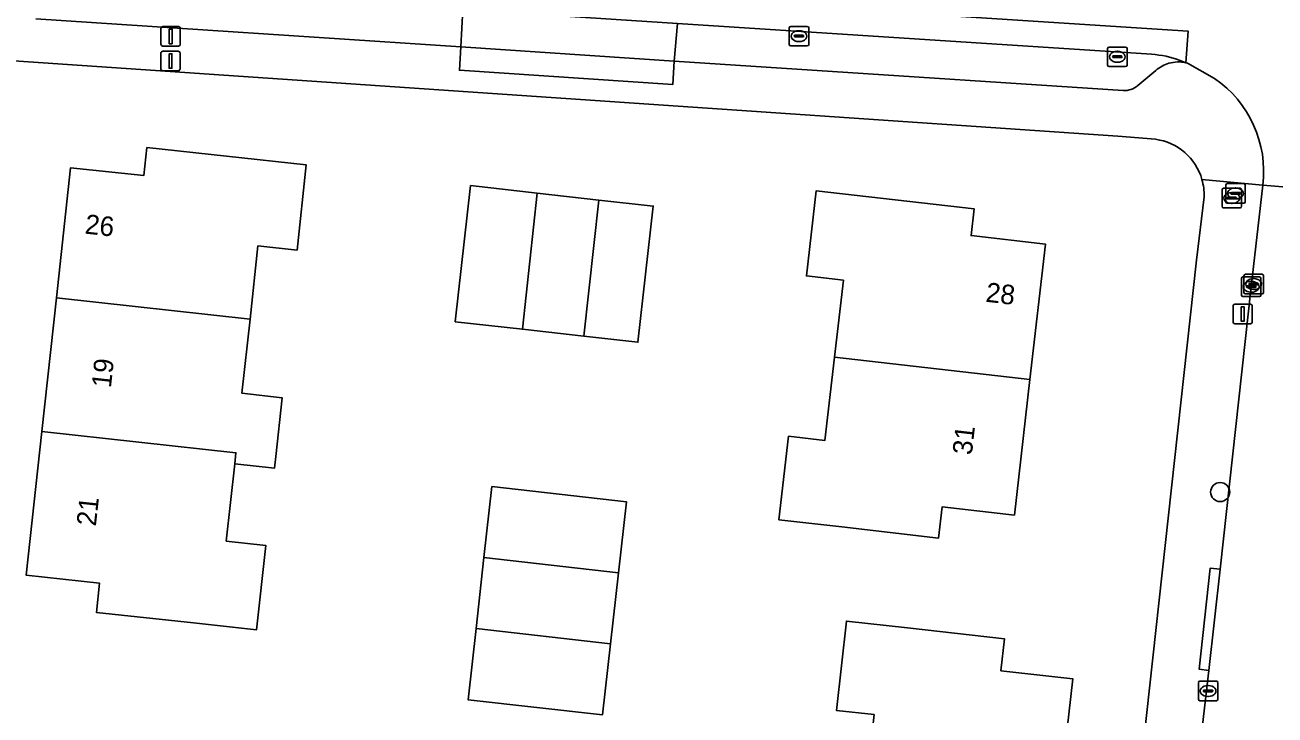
# Model space of a CAD drawing. Extents: x 162396 to 163643, y 386452 to 387406.
# Drawn here: x 162787.9 to 162852, y 386553.7 to 386589 of the extents above; entities that cross this region are included whole.
import ezdxf

# ---------------------------------------------------------------- set-up
doc = ezdxf.new("R2010")
doc.units = 0
for name, color, linetype in [('IMGEO_Boom', 7, 'Continuous'), ('IMGEO_Brandkraan', 7, 'Continuous'), ('IMGEO_Erf', 7, 'Continuous'), ('IMGEO_Kolk', 7, 'Continuous'), ('IMGEO_Lichtmast', 7, 'Continuous'), ('IMGEO_Pand', 7, 'Continuous'), ('IMGEO_Pand_nummerreeks', 7, 'Continuous'), ('IMGEO_Parkeervlak_open', 7, 'Continuous'), ('IMGEO_Rijbaan_lokaal_gesloten', 7, 'Continuous'), ('IMGEO_Rijbaan_lokaal_open', 7, 'Continuous'), ('IMGEO_Voetpad_open', 7, 'Continuous')]:
    doc.layers.add(name, color=color, linetype=linetype)

msp = doc.modelspace()

# ---------------------------------------------------------------- linework, layer by layer
at = {"layer": 'IMGEO_Boom'}
msp.add_circle((162849.181, 386565.089), 0.489, dxfattribs=at)
at = {"layer": 'IMGEO_Brandkraan'}
for p, q in [((162849.465, 386579.97), (162849.465, 386580.822)), ((162849.54, 386580.896), (162850.392, 386580.896)), ((162850.466, 386580.822), (162850.466, 386579.97)), ((162849.275, 386579.733), (162849.275, 386580.585)), ((162849.35, 386580.659), (162850.202, 386580.659)), ((162849.577, 386580.202), (162849.975, 386580.202)), ((162849.724, 386580.39), (162849.724, 386580.402)), ((162849.763, 386580.439), (162849.788, 386580.439)), ((162850.162, 386580.353), (162849.764, 386580.353)), ((162849.767, 386580.439), (162850.165, 386580.439)), ((162849.953, 386580.676), (162849.978, 386580.676)), ((162850.208, 386580.402), (162850.208, 386580.39)), ((162850.276, 386580.585), (162850.276, 386579.733)), ((162850.202, 386579.659), (162849.35, 386579.659)), ((162849.534, 386580.153), (162849.534, 386580.165)), ((162850.392, 386579.896), (162849.54, 386579.896)), ((162849.972, 386580.116), (162849.574, 386580.116)), ((162849.786, 386579.879), (162849.761, 386579.879)), ((162849.976, 386580.116), (162849.951, 386580.116)), ((162850.018, 386580.165), (162850.018, 386580.153))]:
    msp.add_line(p, q, dxfattribs=at)
for points in [[(162849.465, 386579.97), (162849.465, 386580.822)], [(162849.54, 386580.896), (162850.392, 386580.896)], [(162850.466, 386580.822), (162850.466, 386579.97)], [(162849.275, 386579.733), (162849.275, 386580.585)], [(162849.35, 386580.659), (162850.202, 386580.659)], [(162850.276, 386580.585), (162850.276, 386579.733)], [(162850.202, 386579.659), (162849.35, 386579.659)], [(162850.392, 386579.896), (162849.54, 386579.896)]]:
    msp.add_lwpolyline(points, dxfattribs=at)
for centre, radius, start, end in [((162849.542, 386580.82), 0.0765, 91.55205, 178.44795), ((162849.542, 386580.82), 0.0765, 91.55205, 178.44795), ((162850.39, 386580.82), 0.0765, 1.55205, 88.44795), ((162850.39, 386580.82), 0.0765, 1.55205, 88.44795), ((162849.352, 386580.583), 0.0765, 91.55205, 178.44795), ((162849.352, 386580.583), 0.0765, 91.55205, 178.44795), ((162849.574, 386580.162), 0.0403, 85.87752, 175.75265), ((162849.764, 386580.399), 0.0403, 85.87752, 175.75265), ((162849.761, 386580.389), 0.0366, 178.93798, 274.71019), ((162849.979, 386580.164), 0.0386, 1.73085, 96.63898), ((162850.165, 386580.396), 0.043, 264.86636, 352.45326), ((162850.169, 386580.401), 0.0386, 1.73085, 96.63898), ((162850.2, 386580.583), 0.0765, 1.55205, 88.44795), ((162850.2, 386580.583), 0.0765, 1.55205, 88.44795), ((162849.352, 386579.735), 0.0765, 181.55205, 268.44795), ((162849.352, 386579.735), 0.0765, 181.55205, 268.44795), ((162849.542, 386579.972), 0.0765, 181.55205, 268.44795), ((162849.542, 386579.972), 0.0765, 181.55205, 268.44795), ((162849.571, 386580.152), 0.0366, 178.93798, 274.71019), ((162849.975, 386580.159), 0.043, 264.86636, 352.45326), ((162850.2, 386579.735), 0.0765, 271.55205, 358.44795), ((162850.2, 386579.735), 0.0765, 271.55205, 358.44795), ((162850.39, 386579.972), 0.0765, 271.55205, 358.44795), ((162850.39, 386579.972), 0.0765, 271.55205, 358.44795)]:
    msp.add_arc(centre, radius, start, end, dxfattribs=at)
for centre, major_axis, ratio, start_param, end_param in [((162849.762, 386580.159), (-0.387, 0.002), 0.722429, 4.712389, 7.853982), ((162849.952, 386580.396), (-0.387, 0.002), 0.722429, 4.712389, 7.853982), ((162849.787, 386580.159), (-0.39, 0.002), 0.717154, 1.570796, 4.712389), ((162849.977, 386580.396), (-0.39, 0.002), 0.717154, 1.570796, 4.712389)]:
    msp.add_ellipse(centre, major_axis=major_axis, ratio=ratio, start_param=start_param, end_param=end_param, dxfattribs=at)
at = {"layer": 'IMGEO_Erf'}
for points in [[(162845.859, 386583.167), (162843.932, 386583.335), (162785.824, 386587.292), (162782.993, 386561.193), (162787.136, 386530.123), (162840.749, 386537.29)], [(162847.968, 386576.967), (162848.354, 386580.219)], [(162843.962, 386540.573), (162847.968, 386576.967)]]:
    msp.add_lwpolyline(points, dxfattribs=at)
for points in [[(162799.043, 386570.149), (162801.098, 386569.925), (162800.771, 386566.919), (162800.704, 386566.307), (162798.671, 386566.528), (162798.241, 386562.573), (162800.265, 386562.353), (162799.795, 386558.031), (162796.558, 386558.383), (162791.587, 386558.924), (162791.749, 386560.414), (162787.984, 386560.824), (162788.785, 386568.186), (162789.531, 386575.039), (162790.257, 386581.714), (162794.013, 386581.306), (162794.169, 386582.74), (162802.341, 386581.851), (162801.867, 386577.487), (162799.865, 386577.705), (162799.457, 386573.957)], [(162816.567, 386573.079), (162813.421, 386573.432), (162809.976, 386573.819), (162810.76, 386580.795), (162814.181, 386580.411), (162817.33, 386580.057), (162820.12, 386579.744), (162819.336, 386572.768)], [(162838.633, 386563.909), (162834.931, 386564.334), (162834.747, 386562.73), (162829.78, 386563.3), (162826.565, 386563.669), (162827.057, 386567.951), (162828.923, 386567.737), (162829.413, 386572), (162829.866, 386575.947), (162827.977, 386576.164), (162828.478, 386580.532), (162836.572, 386579.603), (162836.414, 386578.23), (162840.227, 386577.793), (162839.43, 386570.852)], [(162818.342, 386560.946), (162817.934, 386557.302), (162817.528, 386553.672), (162817.516, 386553.673), (162810.631, 386554.444), (162811.04, 386558.091), (162811.447, 386561.735), (162811.854, 386565.368), (162818.751, 386564.596)], [(162841.621, 386555.518), (162840.849, 386548.582), (162840.077, 386541.643), (162836.38, 386542.054), (162836.194, 386540.375), (162828.08, 386541.278), (162828.55, 386545.502), (162830.505, 386545.284), (162830.994, 386549.679), (162831.439, 386553.685), (162829.51, 386553.9), (162830.02, 386558.476), (162833.154, 386558.127), (162838.123, 386557.574), (162837.94, 386555.927)]]:
    msp.add_lwpolyline(points, close=True, dxfattribs=at)
for centre, radius, start, end in [((162845.486, 386580.321), 2.871, 15.87582, 82.53151), ((162845.47, 386580.321), 2.885, 357.9719, 15.78496)]:
    msp.add_arc(centre, radius, start, end, dxfattribs=at)
at = {"layer": 'IMGEO_Kolk'}
for p, q in [((162827.093, 386588.029), (162827.093, 386588.881)), ((162827.168, 386588.955), (162828.02, 386588.955)), ((162827.395, 386588.498), (162827.793, 386588.498)), ((162827.581, 386588.735), (162827.606, 386588.735)), ((162828.094, 386588.881), (162828.094, 386588.029)), ((162828.02, 386587.955), (162827.168, 386587.955)), ((162827.352, 386588.449), (162827.352, 386588.461)), ((162827.79, 386588.412), (162827.392, 386588.412)), ((162827.604, 386588.175), (162827.579, 386588.175)), ((162827.836, 386588.461), (162827.836, 386588.449)), ((162843.483, 386587.897), (162844.335, 386587.897)), ((162843.408, 386586.971), (162843.408, 386587.823)), ((162843.667, 386587.391), (162843.667, 386587.403)), ((162844.105, 386587.354), (162843.707, 386587.354)), ((162843.71, 386587.44), (162844.108, 386587.44)), ((162843.896, 386587.677), (162843.921, 386587.677)), ((162844.151, 386587.403), (162844.151, 386587.391)), ((162844.409, 386587.823), (162844.409, 386586.971)), ((162844.335, 386586.897), (162843.483, 386586.897)), ((162843.919, 386587.117), (162843.894, 386587.117)), ((162850.27, 386575.186), (162850.27, 386576.038)), ((162850.345, 386576.112), (162851.197, 386576.112)), ((162850.4, 386575.323), (162850.4, 386576.175)), ((162850.475, 386576.249), (162851.327, 386576.249)), ((162850.659, 386575.743), (162850.659, 386575.755)), ((162851.097, 386575.706), (162850.699, 386575.706)), ((162850.702, 386575.792), (162851.1, 386575.792)), ((162850.758, 386575.892), (162850.783, 386575.892)), ((162850.888, 386576.029), (162850.913, 386576.029)), ((162851.143, 386575.755), (162851.143, 386575.743)), ((162851.271, 386576.038), (162851.271, 386575.186)), ((162851.401, 386576.175), (162851.401, 386575.323)), ((162851.197, 386575.112), (162850.345, 386575.112)), ((162851.327, 386575.249), (162850.475, 386575.249)), ((162850.529, 386575.606), (162850.529, 386575.618)), ((162850.967, 386575.569), (162850.569, 386575.569)), ((162850.572, 386575.655), (162850.97, 386575.655)), ((162850.781, 386575.332), (162850.756, 386575.332)), ((162850.911, 386575.469), (162850.886, 386575.469)), ((162851.013, 386575.618), (162851.013, 386575.606)), ((162848.062, 386554.468), (162848.062, 386555.32)), ((162848.137, 386555.394), (162848.989, 386555.394)), ((162849.063, 386555.32), (162849.063, 386554.468)), ((162848.321, 386554.888), (162848.321, 386554.9)), ((162848.759, 386554.851), (162848.361, 386554.851)), ((162848.364, 386554.937), (162848.762, 386554.937)), ((162848.573, 386554.614), (162848.548, 386554.614)), ((162848.55, 386555.174), (162848.575, 386555.174)), ((162848.805, 386554.9), (162848.805, 386554.888)), ((162848.989, 386554.394), (162848.137, 386554.394))]:
    msp.add_line(p, q, dxfattribs=at)
for points in [[(162827.093, 386588.029), (162827.093, 386588.881)], [(162827.168, 386588.955), (162828.02, 386588.955)], [(162828.094, 386588.881), (162828.094, 386588.029)], [(162828.02, 386587.955), (162827.168, 386587.955)], [(162843.483, 386587.897), (162844.335, 386587.897)], [(162843.408, 386586.971), (162843.408, 386587.823)], [(162844.409, 386587.823), (162844.409, 386586.971)], [(162844.335, 386586.897), (162843.483, 386586.897)], [(162850.27, 386575.186), (162850.27, 386576.038)], [(162850.345, 386576.112), (162851.197, 386576.112)], [(162850.4, 386575.323), (162850.4, 386576.175)], [(162850.475, 386576.249), (162851.327, 386576.249)], [(162851.271, 386576.038), (162851.271, 386575.186)], [(162851.401, 386576.175), (162851.401, 386575.323)], [(162851.197, 386575.112), (162850.345, 386575.112)], [(162851.327, 386575.249), (162850.475, 386575.249)], [(162848.062, 386554.468), (162848.062, 386555.32)], [(162848.137, 386555.394), (162848.989, 386555.394)], [(162849.063, 386555.32), (162849.063, 386554.468)], [(162848.989, 386554.394), (162848.137, 386554.394)]]:
    msp.add_lwpolyline(points, dxfattribs=at)
for centre, radius, start, end in [((162827.17, 386588.879), 0.0765, 91.55205, 178.44795), ((162827.17, 386588.879), 0.0765, 91.55205, 178.44795), ((162827.392, 386588.458), 0.0403, 85.87752, 175.75265), ((162827.797, 386588.46), 0.0386, 1.73085, 96.63898), ((162828.018, 386588.879), 0.0765, 1.55205, 88.44795), ((162828.018, 386588.879), 0.0765, 1.55205, 88.44795), ((162827.17, 386588.031), 0.0765, 181.55205, 268.44795), ((162827.17, 386588.031), 0.0765, 181.55205, 268.44795), ((162827.389, 386588.448), 0.0366, 178.93798, 274.71019), ((162827.793, 386588.455), 0.043, 264.86636, 352.45326), ((162828.018, 386588.031), 0.0765, 271.55205, 358.44795), ((162828.018, 386588.031), 0.0765, 271.55205, 358.44795), ((162843.485, 386587.821), 0.0765, 91.55205, 178.44795), ((162843.485, 386587.821), 0.0765, 91.55205, 178.44795), ((162844.333, 386587.821), 0.0765, 1.55205, 88.44795), ((162844.333, 386587.821), 0.0765, 1.55205, 88.44795), ((162843.707, 386587.4), 0.0403, 85.87752, 175.75265), ((162843.704, 386587.39), 0.0366, 178.93798, 274.71019), ((162844.108, 386587.397), 0.043, 264.86636, 352.45326), ((162844.112, 386587.402), 0.0386, 1.73085, 96.63898), ((162843.485, 386586.973), 0.0765, 181.55205, 268.44795), ((162843.485, 386586.973), 0.0765, 181.55205, 268.44795), ((162844.333, 386586.973), 0.0765, 271.55205, 358.44795), ((162844.333, 386586.973), 0.0765, 271.55205, 358.44795), ((162850.347, 386576.036), 0.0765, 91.55205, 178.44795), ((162850.347, 386576.036), 0.0765, 91.55205, 178.44795), ((162850.477, 386576.173), 0.0765, 91.55205, 178.44795), ((162850.477, 386576.173), 0.0765, 91.55205, 178.44795), ((162850.699, 386575.752), 0.0403, 85.87752, 175.75265), ((162850.696, 386575.742), 0.0366, 178.93798, 274.71019), ((162851.1, 386575.749), 0.043, 264.86636, 352.45326), ((162851.104, 386575.754), 0.0386, 1.73085, 96.63898), ((162851.195, 386576.036), 0.0765, 1.55205, 88.44795), ((162851.195, 386576.036), 0.0765, 1.55205, 88.44795), ((162851.325, 386576.173), 0.0765, 1.55205, 88.44795), ((162851.325, 386576.173), 0.0765, 1.55205, 88.44795), ((162850.347, 386575.188), 0.0765, 181.55205, 268.44795), ((162850.347, 386575.188), 0.0765, 181.55205, 268.44795), ((162850.477, 386575.325), 0.0765, 181.55205, 268.44795), ((162850.477, 386575.325), 0.0765, 181.55205, 268.44795), ((162850.569, 386575.615), 0.0403, 85.87752, 175.75265), ((162850.566, 386575.605), 0.0366, 178.93798, 274.71019), ((162850.97, 386575.612), 0.043, 264.86636, 352.45326), ((162850.974, 386575.617), 0.0386, 1.73085, 96.63898), ((162851.195, 386575.188), 0.0765, 271.55205, 358.44795), ((162851.195, 386575.188), 0.0765, 271.55205, 358.44795), ((162851.325, 386575.325), 0.0765, 271.55205, 358.44795), ((162851.325, 386575.325), 0.0765, 271.55205, 358.44795), ((162848.139, 386555.318), 0.0765, 91.55205, 178.44795), ((162848.139, 386555.318), 0.0765, 91.55205, 178.44795), ((162848.987, 386555.318), 0.0765, 1.55205, 88.44795), ((162848.987, 386555.318), 0.0765, 1.55205, 88.44795), ((162848.361, 386554.897), 0.0403, 85.87752, 175.75265), ((162848.358, 386554.887), 0.0366, 178.93798, 274.71019), ((162848.762, 386554.894), 0.043, 264.86636, 352.45326), ((162848.766, 386554.899), 0.0386, 1.73085, 96.63898), ((162848.139, 386554.47), 0.0765, 181.55205, 268.44795), ((162848.139, 386554.47), 0.0765, 181.55205, 268.44795), ((162848.987, 386554.47), 0.0765, 271.55205, 358.44795), ((162848.987, 386554.47), 0.0765, 271.55205, 358.44795)]:
    msp.add_arc(centre, radius, start, end, dxfattribs=at)
for centre, major_axis, ratio, start_param, end_param in [((162827.58, 386588.455), (-0.387, 0.002), 0.722429, 4.712389, 7.853982), ((162827.605, 386588.455), (-0.39, 0.002), 0.717154, 1.570796, 4.712389), ((162843.895, 386587.397), (-0.387, 0.002), 0.722429, 4.712389, 7.853982), ((162843.92, 386587.397), (-0.39, 0.002), 0.717154, 1.570796, 4.712389), ((162850.757, 386575.612), (-0.387, 0.002), 0.722429, 4.712389, 7.853982), ((162850.887, 386575.749), (-0.387, 0.002), 0.722429, 4.712389, 7.853982), ((162850.782, 386575.612), (-0.39, 0.002), 0.717154, 1.570796, 4.712389), ((162850.912, 386575.749), (-0.39, 0.002), 0.717154, 1.570796, 4.712389), ((162848.549, 386554.894), (-0.387, 0.002), 0.722429, 4.712389, 7.853982), ((162848.574, 386554.894), (-0.39, 0.002), 0.717154, 1.570796, 4.712389)]:
    msp.add_ellipse(centre, major_axis=major_axis, ratio=ratio, start_param=start_param, end_param=end_param, dxfattribs=at)
at = {"layer": 'IMGEO_Lichtmast'}
for p, q in [((162794.893, 386588.042), (162794.893, 386588.842)), ((162794.893, 386588.842), (162794.893, 386588.042)), ((162794.993, 386588.942), (162795.783, 386588.942)), ((162795.783, 386588.942), (162794.993, 386588.942)), ((162795.883, 386588.842), (162795.883, 386588.042)), ((162795.883, 386588.042), (162795.883, 386588.842)), ((162795.783, 386587.942), (162794.993, 386587.942)), ((162794.993, 386587.942), (162795.783, 386587.942)), ((162794.885, 386586.781), (162794.885, 386587.581)), ((162794.885, 386587.581), (162794.885, 386586.781)), ((162794.985, 386587.681), (162795.775, 386587.681)), ((162795.775, 386587.681), (162794.985, 386587.681)), ((162795.875, 386587.581), (162795.875, 386586.781)), ((162795.875, 386586.781), (162795.875, 386587.581)), ((162795.775, 386586.681), (162794.985, 386586.681)), ((162794.985, 386586.681), (162795.775, 386586.681)), ((162849.837, 386573.815), (162849.837, 386574.615)), ((162849.837, 386574.615), (162849.837, 386573.815)), ((162849.937, 386574.715), (162850.727, 386574.715)), ((162850.727, 386574.715), (162849.937, 386574.715)), ((162850.827, 386574.615), (162850.827, 386573.815)), ((162850.827, 386573.815), (162850.827, 386574.615)), ((162850.727, 386573.715), (162849.937, 386573.715)), ((162849.937, 386573.715), (162850.727, 386573.715))]:
    msp.add_line(p, q, dxfattribs=at)
for points in [[(162795.313, 386588.817), (162795.463, 386588.817), (162795.463, 386588.067), (162795.313, 386588.067), (162795.313, 386588.817)], [(162795.305, 386587.556), (162795.455, 386587.556), (162795.455, 386586.806), (162795.305, 386586.806), (162795.305, 386587.556)], [(162850.257, 386574.59), (162850.407, 386574.59), (162850.407, 386573.84), (162850.257, 386573.84), (162850.257, 386574.59)]]:
    msp.add_lwpolyline(points, dxfattribs=at)
for centre, start, end in [((162794.993, 386588.842), 90, 180), ((162794.993, 386588.842), 90, 180), ((162795.783, 386588.842), 0, 90), ((162795.783, 386588.842), 360, 90), ((162794.993, 386588.042), 180, 270), ((162794.993, 386588.042), 180, 270), ((162795.783, 386588.042), 270, 0), ((162795.783, 386588.042), 270, 0), ((162794.985, 386587.581), 90, 180), ((162794.985, 386587.581), 90, 180), ((162795.775, 386587.581), 0, 90), ((162795.775, 386587.581), 360, 90), ((162794.985, 386586.781), 180, 270), ((162794.985, 386586.781), 180, 270), ((162795.775, 386586.781), 270, 0), ((162795.775, 386586.781), 270, 0), ((162849.937, 386574.615), 90, 180), ((162849.937, 386574.615), 90, 180), ((162850.727, 386574.615), 0, 90), ((162850.727, 386574.615), 360, 90), ((162849.937, 386573.815), 180, 270), ((162849.937, 386573.815), 180, 270), ((162850.727, 386573.815), 270, 0), ((162850.727, 386573.815), 270, 0)]:
    msp.add_arc(centre, 0.1, start, end, dxfattribs=at)
at = {"layer": 'IMGEO_Pand'}
for points in [[(162799.457, 386573.957), (162799.865, 386577.705), (162801.867, 386577.487), (162802.341, 386581.851), (162794.169, 386582.74), (162794.013, 386581.306), (162790.257, 386581.714), (162789.531, 386575.039)], [(162814.181, 386580.411), (162810.76, 386580.795), (162809.976, 386573.819), (162813.421, 386573.432)], [(162817.33, 386580.057), (162814.181, 386580.411), (162813.421, 386573.432), (162816.567, 386573.079)], [(162839.43, 386570.852), (162840.227, 386577.793), (162836.414, 386578.23), (162836.572, 386579.603), (162828.478, 386580.532), (162827.977, 386576.164), (162829.866, 386575.947), (162829.413, 386572)], [(162817.33, 386580.057), (162816.567, 386573.079), (162819.336, 386572.768), (162820.12, 386579.744)], [(162799.457, 386573.957), (162789.531, 386575.039), (162788.785, 386568.186), (162798.734, 386567.105), (162798.671, 386566.528), (162800.704, 386566.307), (162800.771, 386566.919), (162801.098, 386569.925), (162799.043, 386570.149)], [(162829.413, 386572), (162828.923, 386567.737), (162827.057, 386567.951), (162826.565, 386563.669), (162829.78, 386563.3), (162834.747, 386562.73), (162834.931, 386564.334), (162838.633, 386563.909), (162839.43, 386570.852)], [(162798.671, 386566.528), (162798.734, 386567.105), (162788.785, 386568.186), (162787.984, 386560.824), (162791.749, 386560.414), (162791.587, 386558.924), (162796.558, 386558.383), (162799.795, 386558.031), (162800.265, 386562.353), (162798.241, 386562.573)], [(162818.342, 386560.946), (162818.751, 386564.596), (162811.854, 386565.368), (162811.447, 386561.735)], [(162817.934, 386557.302), (162818.342, 386560.946), (162811.447, 386561.735), (162811.04, 386558.091)], [(162840.849, 386548.582), (162841.621, 386555.518), (162837.94, 386555.927), (162838.123, 386557.574), (162833.154, 386558.127), (162830.02, 386558.476), (162829.51, 386553.9), (162831.439, 386553.685), (162830.994, 386549.679)], [(162811.04, 386558.091), (162810.631, 386554.444), (162817.516, 386553.673), (162817.528, 386553.672), (162817.934, 386557.302)]]:
    msp.add_lwpolyline(points, close=True, dxfattribs=at)
at = {"layer": 'IMGEO_Parkeervlak_open'}
for points in [[(162788.479, 386589.349), (162810.269, 386587.907), (162810.36, 386589.818), (162785.991, 386591.401)], [(162821.37, 386589.103), (162821.202, 386587.174), (162827.484, 386586.769), (162844.212, 386585.667)], [(162845.666, 386587.525), (162821.37, 386589.103)], [(162844.956, 386585.925), (162845.881, 386586.701)], [(162847.418, 386587.095), (162847.122, 386587.208)]]:
    msp.add_lwpolyline(points, dxfattribs=at)
for centre, radius, start, end in [((162845.342, 386582.534), 5.001, 69.15023, 86.28428), ((162847.049, 386585.335), 1.797, 105.95173, 130.52805), ((162847.052, 386585.325), 1.808, 78.30639, 105.94072), ((162844.257, 386586.739), 1.073, 267.59117, 310.65928)]:
    msp.add_arc(centre, radius, start, end, dxfattribs=at)
at = {"layer": 'IMGEO_Rijbaan_lokaal_gesloten'}
for points in [[(162847.122, 386587.208), (162847.418, 386587.095), (162847.539, 386588.706), (162827.674, 386589.983), (162821.296, 386590.405), (162810.392, 386591.122), (162792.843, 386592.298)], [(162785.991, 386591.401), (162810.36, 386589.818), (162821.37, 386589.103), (162845.666, 386587.525)]]:
    msp.add_lwpolyline(points, dxfattribs=at)
msp.add_arc((162845.342, 386582.534), 5.001, 69.15023, 86.28428, dxfattribs=at)
at = {"layer": 'IMGEO_Rijbaan_lokaal_open'}
for points in [[(162777.205, 386597.414), (162777.106, 386596.182), (162742.964, 386598.357), (162729.614, 386599.202), (162729.422, 386596.356), (162742.035, 386595.583), (162758.459, 386594.528), (162779.404, 386593.181), (162792.843, 386592.298), (162810.392, 386591.122), (162821.296, 386590.405), (162827.674, 386589.983), (162847.539, 386588.706), (162847.418, 386587.095), (162847.502, 386587.063), (162848.895, 386586.285)], [(162852.625, 386539.029), (162852.755, 386539.186), (162852.781, 386539.88), (162853.528, 386546.753), (162853.97, 386550.062), (162854.049, 386550.493), (162856.469, 386571.462), (162856.501, 386571.743), (162856.935, 386575.645), (162857.183, 386578.729), (162857.311, 386580.324), (162851.366, 386580.816), (162850.771, 386575.612), (162849.175, 386561.132), (162848.605, 386555.948), (162846.636, 386538.981)], [(162851.366, 386580.816), (162857.311, 386580.324), (162857.343, 386580.725)]]:
    msp.add_lwpolyline(points, dxfattribs=at)
msp.add_lwpolyline([(162821.37, 386589.103), (162810.36, 386589.818), (162810.269, 386587.907), (162821.202, 386587.174)], close=True, dxfattribs=at)
msp.add_arc((162845.625, 386581.515), 5.784, 353.06207, 55.56668, dxfattribs=at)
at = {"layer": 'IMGEO_Voetpad_open'}
for points in [[(162667.469, 386594.822), (162669.061, 386594.718), (162669.213, 386594.709), (162714.198, 386591.871), (162717.227, 386591.629), (162774.713, 386588.018), (162782.906, 386587.503), (162785.824, 386587.292), (162843.932, 386583.335), (162845.859, 386583.167)], [(162844.212, 386585.667), (162827.484, 386586.769), (162821.202, 386587.174), (162821.135, 386585.978), (162810.188, 386586.71), (162810.269, 386587.907), (162788.479, 386589.349)], [(162845.881, 386586.701), (162844.956, 386585.925)], [(162848.895, 386586.285), (162847.502, 386587.063), (162847.418, 386587.095)], [(162846.636, 386538.981), (162848.605, 386555.948), (162848.105, 386556.008), (162848.675, 386561.192), (162849.175, 386561.132), (162850.771, 386575.612), (162851.366, 386580.816), (162848.247, 386581.106)], [(162848.247, 386581.106), (162851.366, 386580.816)], [(162848.354, 386580.219), (162847.968, 386576.967), (162843.962, 386540.573)]]:
    msp.add_lwpolyline(points, dxfattribs=at)
for points in [[(162821.202, 386587.174), (162810.269, 386587.907), (162810.188, 386586.71), (162821.135, 386585.978)], [(162849.175, 386561.132), (162848.675, 386561.192), (162848.105, 386556.008), (162848.605, 386555.948)]]:
    msp.add_lwpolyline(points, close=True, dxfattribs=at)
for centre, radius, start, end in [((162847.049, 386585.335), 1.797, 105.95173, 130.52805), ((162847.052, 386585.325), 1.808, 78.30639, 105.94072), ((162845.625, 386581.515), 5.784, 353.06207, 55.56668), ((162844.257, 386586.739), 1.073, 267.59117, 310.65928), ((162845.486, 386580.321), 2.871, 15.87582, 82.53151), ((162845.47, 386580.321), 2.885, 357.9719, 15.78496)]:
    msp.add_arc(centre, radius, start, end, dxfattribs=at)

# ---------------------------------------------------------------- texts
at = {"layer": 'IMGEO_Pand_nummerreeks'}
for s, rotation, p in [('26', 353.80049, (162790.96, 386578.339)), ('28', 353.46197, (162837.129, 386574.847)), ('19', 83.78935, (162792.325, 386570.399)), ('31', 83.45064, (162836.446, 386566.959)), ('21', 83.78935, (162791.554, 386563.313))]:
    msp.add_text(s, height=1, rotation=rotation, dxfattribs=at).set_placement(p)

doc.saveas('drawing.dxf')
